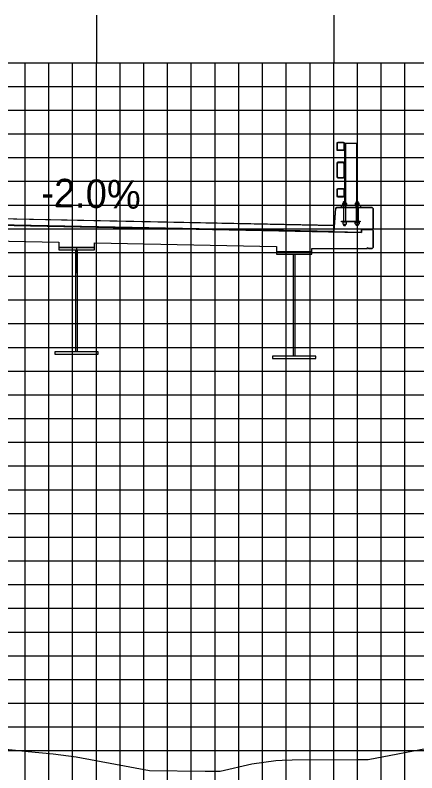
# Model space of a CAD drawing. Extents: x 1790124 to 1790467, y 442591 to 442811.
# Drawn here: x 1790296.28 to 1790313.2, y 442688.73 to 442720.67 of the extents above; entities that cross this region are included whole.
import ezdxf

# ---------------------------------------------------------------- set-up
doc = ezdxf.new("R2010")
doc.units = 0
for name, color, linetype in [('ANNOTATION', 7, 'Continuous'), ('BORDER', 7, 'Continuous'), ('D_Bridge_Framing', 7, 'Continuous'), ('D_Bridge_Railing', 7, 'Continuous'), ('D_Bridge_Superstructure', 7, 'Continuous'), ('MAJOR', 7, 'Continuous'), ('MINOR', 7, 'Continuous'), ('PATTERNING', 7, 'Continuous'), ('S_Roadway_Centerline', 7, 'Continuous'), ('SHADING', 7, 'Continuous')]:
    doc.layers.add(name, color=color, linetype=linetype)

msp = doc.modelspace()

# ---------------------------------------------------------------- linework, layer by layer
at = {"layer": 'BORDER'}
msp.add_line((1790298.862, 442710.837), (1790298.862, 442709.799), dxfattribs=at)
at = {"layer": 'D_Bridge_Framing'}
for points in [[(1790298.112, 442710.774), (1790299.612, 442710.774), (1790299.612, 442710.878), (1790298.112, 442710.878)], [(1790298.839, 442710.774), (1790298.886, 442710.774), (1790298.886, 442706.482), (1790298.839, 442706.482)], [(1790307.279, 442710.591), (1790308.779, 442710.591), (1790308.779, 442710.695), (1790307.279, 442710.695)], [(1790308.006, 442710.591), (1790308.053, 442710.591), (1790308.053, 442706.299), (1790308.006, 442706.299)], [(1790297.946, 442706.378), (1790299.779, 442706.378), (1790299.779, 442706.482), (1790297.946, 442706.482)], [(1790307.112, 442706.195), (1790308.946, 442706.195), (1790308.946, 442706.299), (1790307.112, 442706.299)]]:
    msp.add_lwpolyline(points, close=True, dxfattribs=at)
at = {"layer": 'D_Bridge_Railing'}
for p, q in [((1790309.821, 442715.264), (1790309.821, 442715.014)), ((1790309.842, 442715.264), (1790309.842, 442715.014)), ((1790310.113, 442715.306), (1790309.862, 442715.306)), ((1790310.113, 442715.285), (1790309.862, 442715.285)), ((1790310.133, 442715.014), (1790310.133, 442715.264)), ((1790310.154, 442715.014), (1790310.154, 442715.264)), ((1790310.154, 442715.264), (1790310.154, 442712.807)), ((1790310.685, 442715.264), (1790310.154, 442715.264)), ((1790310.191, 442715.264), (1790310.191, 442712.802)), ((1790310.649, 442715.264), (1790310.649, 442712.802)), ((1790310.685, 442715.264), (1790310.685, 442712.807)), ((1790309.862, 442714.993), (1790310.113, 442714.993)), ((1790309.862, 442714.972), (1790310.113, 442714.972)), ((1790309.821, 442714.421), (1790309.821, 442713.858)), ((1790309.847, 442714.421), (1790309.847, 442713.858)), ((1790310.102, 442714.472), (1790309.873, 442714.472)), ((1790310.102, 442714.446), (1790309.873, 442714.446)), ((1790310.128, 442713.858), (1790310.128, 442714.421)), ((1790310.154, 442713.858), (1790310.154, 442714.421)), ((1790309.873, 442713.832), (1790310.102, 442713.832)), ((1790309.873, 442713.806), (1790310.102, 442713.806)), ((1790309.821, 442713.306), (1790309.821, 442713.056)), ((1790309.842, 442713.306), (1790309.842, 442713.056)), ((1790310.113, 442713.347), (1790309.862, 442713.347)), ((1790310.113, 442713.327), (1790309.862, 442713.327)), ((1790310.133, 442713.056), (1790310.133, 442713.306)), ((1790310.154, 442713.056), (1790310.154, 442713.306)), ((1790309.862, 442713.035), (1790310.113, 442713.035)), ((1790309.862, 442713.014), (1790310.113, 442713.014)), ((1790310.112, 442712.797), (1790310.196, 442712.797)), ((1790310.154, 442712.807), (1790310.154, 442712.65)), ((1790310.727, 442712.797), (1790310.644, 442712.797)), ((1790310.685, 442712.807), (1790310.685, 442712.65)), ((1790310.112, 442712.556), (1790310.112, 442712.65)), ((1790310.113, 442712.735), (1790310.113, 442712.672)), ((1790310.195, 442712.735), (1790310.195, 442712.672)), ((1790310.196, 442712.556), (1790310.196, 442712.65)), ((1790310.644, 442712.735), (1790310.644, 442712.672)), ((1790310.644, 442712.556), (1790310.644, 442712.65)), ((1790310.726, 442712.735), (1790310.726, 442712.672)), ((1790310.727, 442712.556), (1790310.727, 442712.65)), ((1790310.112, 442711.986), (1790310.112, 442711.954)), ((1790310.196, 442711.986), (1790310.196, 442711.954)), ((1790310.644, 442711.986), (1790310.644, 442711.954)), ((1790310.727, 442711.986), (1790310.727, 442711.954))]:
    msp.add_line(p, q, dxfattribs=at)
for points in [[(1790310.112, 442712.745), (1790310.112, 442712.797), (1790310.123, 442712.807), (1790310.185, 442712.807), (1790310.196, 442712.797), (1790310.196, 442712.745)], [(1790310.727, 442712.745), (1790310.727, 442712.797), (1790310.717, 442712.807), (1790310.654, 442712.807), (1790310.644, 442712.797), (1790310.644, 442712.745)], [(1790310.112, 442712.556), (1790310.112, 442711.986)], [(1790310.196, 442712.556), (1790310.196, 442711.986)], [(1790310.644, 442712.556), (1790310.644, 442711.986)], [(1790310.727, 442712.556), (1790310.727, 442711.986)], [(1790310.241, 442711.954), (1790310.241, 442711.941), (1790310.067, 442711.941), (1790310.067, 442711.954)], [(1790310.088, 442711.941), (1790310.072, 442711.932), (1790310.072, 442711.869), (1790310.088, 442711.859), (1790310.22, 442711.859), (1790310.236, 442711.869), (1790310.236, 442711.932), (1790310.22, 442711.941)], [(1790310.112, 442711.859), (1790310.112, 442711.818), (1790310.123, 442711.807), (1790310.185, 442711.807), (1790310.196, 442711.818), (1790310.196, 442711.859)], [(1790310.599, 442711.954), (1790310.599, 442711.941), (1790310.772, 442711.941), (1790310.772, 442711.954)], [(1790310.751, 442711.941), (1790310.768, 442711.932), (1790310.768, 442711.869), (1790310.751, 442711.859), (1790310.619, 442711.859), (1790310.603, 442711.869), (1790310.603, 442711.932), (1790310.619, 442711.941)], [(1790310.727, 442711.859), (1790310.727, 442711.818), (1790310.717, 442711.807), (1790310.654, 442711.807), (1790310.644, 442711.818), (1790310.644, 442711.859)]]:
    msp.add_lwpolyline(points, dxfattribs=at)
for points in [[(1790310.836, 442712.65), (1790310.003, 442712.65), (1790310.003, 442712.566), (1790310.836, 442712.566)], [(1790310.836, 442712.566), (1790310.003, 442712.566), (1790310.003, 442712.556), (1790310.836, 442712.556)], [(1790310.067, 442712.65), (1790310.241, 442712.65), (1790310.241, 442712.663), (1790310.067, 442712.663)], [(1790310.072, 442712.735), (1790310.088, 442712.745), (1790310.22, 442712.745), (1790310.236, 442712.735), (1790310.236, 442712.672), (1790310.22, 442712.663), (1790310.088, 442712.663), (1790310.072, 442712.672)], [(1790310.772, 442712.65), (1790310.599, 442712.65), (1790310.599, 442712.663), (1790310.772, 442712.663)], [(1790310.768, 442712.735), (1790310.751, 442712.745), (1790310.619, 442712.745), (1790310.603, 442712.735), (1790310.603, 442712.672), (1790310.619, 442712.663), (1790310.751, 442712.663), (1790310.768, 442712.672)], [(1790310.029, 442711.986), (1790310.81, 442711.986), (1790310.81, 442711.954), (1790310.029, 442711.954)]]:
    msp.add_lwpolyline(points, close=True, dxfattribs=at)
for centre, radius, start, end in [((1790309.862, 442715.264), 0.0415, 90, 180), ((1790309.862, 442715.264), 0.0206, 90, 180), ((1790310.113, 442715.264), 0.0415, 0, 90), ((1790310.113, 442715.264), 0.0206, 0, 90), ((1790309.862, 442715.014), 0.0415, 180, 270), ((1790309.862, 442715.014), 0.0206, 180, 270), ((1790310.113, 442715.014), 0.0415, 270, 0), ((1790310.113, 442715.014), 0.0206, 270, 0), ((1790309.873, 442714.421), 0.0518, 90, 180), ((1790309.873, 442714.421), 0.0257, 90, 180), ((1790310.102, 442714.421), 0.0518, 0, 90), ((1790310.102, 442714.421), 0.0257, 0, 90), ((1790309.873, 442713.858), 0.0518, 180, 270), ((1790309.873, 442713.858), 0.0257, 180, 270), ((1790310.102, 442713.858), 0.0518, 270, 0), ((1790310.102, 442713.858), 0.0257, 270, 360), ((1790309.862, 442713.306), 0.0415, 90, 180), ((1790309.862, 442713.306), 0.0206, 90, 180), ((1790310.113, 442713.306), 0.0415, 0, 90), ((1790310.113, 442713.306), 0.0206, 0, 90), ((1790309.862, 442713.056), 0.0415, 180, 270), ((1790309.862, 442713.056), 0.0206, 180, 270), ((1790310.113, 442713.056), 0.0415, 270, 0), ((1790310.113, 442713.056), 0.0206, 270, 0), ((1790310.093, 442712.706), 0.036, 55.4339, 120), ((1790310.093, 442712.702), 0.036, 240, 304.5661), ((1790310.154, 442712.606), 0.136, 72.412, 107.588), ((1790310.154, 442712.802), 0.136, 252.412, 287.588), ((1790310.216, 442712.706), 0.036, 60, 124.5661), ((1790310.216, 442712.702), 0.036, 235.4339, 300), ((1790310.624, 442712.706), 0.036, 55.4339, 120), ((1790310.624, 442712.702), 0.036, 240, 304.5661), ((1790310.685, 442712.606), 0.136, 72.412, 107.588), ((1790310.685, 442712.802), 0.136, 252.412, 287.588), ((1790310.747, 442712.706), 0.036, 60, 124.5661), ((1790310.747, 442712.702), 0.036, 235.4339, 300)]:
    msp.add_arc(centre, radius, start, end, dxfattribs=at)
at = {"layer": 'D_Bridge_Superstructure'}
for p, q in [((1790309.776, 442712.514), (1790309.696, 442711.537)), ((1790309.776, 442712.514), (1790309.821, 442712.556)), ((1790309.821, 442712.556), (1790311.321, 442712.556)), ((1790311.362, 442712.514), (1790311.321, 442712.556)), ((1790311.362, 442712.514), (1790311.362, 442711.68)), ((1790289.696, 442712.207), (1790309.718, 442711.807)), ((1790289.696, 442711.957), (1790309.697, 442711.557)), ((1790289.696, 442711.937), (1790310.862, 442711.513)), ((1790309.696, 442711.537), (1790289.696, 442711.937)), ((1790310.862, 442711.513), (1790309.696, 442711.537)), ((1790310.862, 442711.638), (1790310.862, 442711.513)), ((1790310.862, 442711.638), (1790311.321, 442711.638)), ((1790311.321, 442711.638), (1790310.862, 442711.638)), ((1790310.862, 442711.638), (1790310.862, 442711.513)), ((1790311.321, 442711.638), (1790311.362, 442711.68)), ((1790298.112, 442710.878), (1790299.612, 442710.878)), ((1790307.279, 442710.695), (1790308.779, 442710.695)), ((1790311.112, 442710.837), (1790311.112, 442710.878)), ((1790311.112, 442710.878), (1790311.154, 442710.837))]:
    msp.add_line(p, q, dxfattribs=at)
for points in [[(1790311.321, 442711.638), (1790311.362, 442711.597), (1790311.362, 442710.878), (1790311.321, 442710.837), (1790311.154, 442710.837)], [(1790311.154, 442710.837), (1790311.321, 442710.837), (1790311.362, 442710.878), (1790311.362, 442711.597), (1790311.321, 442711.638)], [(1790290.446, 442711.062), (1790290.446, 442711.255), (1790298.112, 442711.102), (1790298.112, 442710.878)], [(1790299.612, 442710.878), (1790299.612, 442711.072), (1790307.279, 442710.918), (1790307.279, 442710.695)], [(1790308.779, 442710.695), (1790308.779, 442710.837), (1790311.112, 442710.837)], [(1790311.112, 442710.878), (1790311.112, 442710.837)], [(1790311.112, 442710.878), (1790311.154, 442710.837)]]:
    msp.add_lwpolyline(points, dxfattribs=at)
at = {"layer": 'MAJOR'}
for p, q in [((1790299.696, 442720.669), (1790299.696, 442718.665)), ((1790309.696, 442720.669), (1790309.696, 442718.665)), ((1790149.696, 442718.665), (1790429.696, 442718.665)), ((1790149.696, 442718.665), (1790429.696, 442718.665)), ((1790299.696, 442673.665), (1790299.696, 442718.665)), ((1790309.696, 442673.665), (1790309.696, 442718.665)), ((1790149.696, 442713.665), (1790429.696, 442713.665)), ((1790149.696, 442708.665), (1790429.696, 442708.665)), ((1790149.696, 442703.665), (1790429.696, 442703.665)), ((1790149.696, 442698.665), (1790429.696, 442698.665)), ((1790149.696, 442693.665), (1790429.696, 442693.665))]:
    msp.add_line(p, q, dxfattribs=at)
at = {"layer": 'MINOR'}
for p, q in [((1790296.696, 442673.665), (1790296.696, 442718.665)), ((1790297.696, 442673.665), (1790297.696, 442718.665)), ((1790298.696, 442673.665), (1790298.696, 442718.665)), ((1790300.696, 442673.665), (1790300.696, 442718.665)), ((1790301.696, 442673.665), (1790301.696, 442718.665)), ((1790302.696, 442673.665), (1790302.696, 442718.665)), ((1790303.696, 442673.665), (1790303.696, 442718.665)), ((1790304.696, 442673.665), (1790304.696, 442718.665)), ((1790305.696, 442673.665), (1790305.696, 442718.665)), ((1790306.696, 442673.665), (1790306.696, 442718.665)), ((1790307.696, 442673.665), (1790307.696, 442718.665)), ((1790308.696, 442673.665), (1790308.696, 442718.665)), ((1790310.696, 442673.665), (1790310.696, 442718.665)), ((1790311.696, 442673.665), (1790311.696, 442718.665)), ((1790312.696, 442673.665), (1790312.696, 442718.665)), ((1790149.696, 442717.665), (1790429.696, 442717.665)), ((1790149.696, 442716.665), (1790429.696, 442716.665)), ((1790149.696, 442715.665), (1790429.696, 442715.665)), ((1790149.696, 442714.665), (1790429.696, 442714.665)), ((1790149.696, 442712.665), (1790429.696, 442712.665)), ((1790149.696, 442711.665), (1790429.696, 442711.665)), ((1790149.696, 442710.665), (1790429.696, 442710.665)), ((1790149.696, 442709.665), (1790429.696, 442709.665)), ((1790149.696, 442707.665), (1790429.696, 442707.665)), ((1790149.696, 442706.665), (1790429.696, 442706.665)), ((1790149.696, 442705.665), (1790429.696, 442705.665)), ((1790149.696, 442704.665), (1790429.696, 442704.665)), ((1790149.696, 442702.665), (1790429.696, 442702.665)), ((1790149.696, 442701.665), (1790429.696, 442701.665)), ((1790149.696, 442700.665), (1790429.696, 442700.665)), ((1790149.696, 442699.665), (1790429.696, 442699.665)), ((1790149.696, 442697.665), (1790429.696, 442697.665)), ((1790149.696, 442696.665), (1790429.696, 442696.665)), ((1790149.696, 442695.665), (1790429.696, 442695.665)), ((1790149.696, 442694.665), (1790429.696, 442694.665)), ((1790149.696, 442692.665), (1790429.696, 442692.665)), ((1790149.696, 442691.665), (1790429.696, 442691.665)), ((1790149.696, 442690.665), (1790429.696, 442690.665)), ((1790149.696, 442689.665), (1790429.696, 442689.665))]:
    msp.add_line(p, q, dxfattribs=at)
at = {"layer": 'PATTERNING'}
for p, q in [((1790309.821, 442712.556), (1790309.776, 442712.514)), ((1790311.321, 442712.556), (1790309.821, 442712.556)), ((1790311.362, 442712.514), (1790311.321, 442712.556)), ((1790311.362, 442711.68), (1790311.362, 442712.514)), ((1790309.696, 442711.537), (1790310.862, 442711.513)), ((1790310.862, 442711.513), (1790310.862, 442711.638)), ((1790310.862, 442711.638), (1790311.321, 442711.638)), ((1790311.321, 442711.638), (1790311.362, 442711.68))]:
    msp.add_line(p, q, dxfattribs=at)
msp.add_lwpolyline([(1790309.776, 442712.514), (1790309.718, 442711.807), (1790309.697, 442711.557), (1790309.696, 442711.537)], dxfattribs=at)
at = {"layer": 'S_Roadway_Centerline'}
msp.add_lwpolyline([(1790294.527, 442689.874), (1790296.831, 442689.629), (1790297.881, 442689.537), (1790298.84, 442689.403), (1790301.935, 442688.832), (1790304.276, 442688.796), (1790304.907, 442688.793), (1790306.245, 442689.105), (1790307.261, 442689.253), (1790307.527, 442689.266), (1790307.951, 442689.284), (1790310.695, 442689.293), (1790311.142, 442689.289), (1790316.737, 442690.355)], dxfattribs=at)
at = {"layer": 'SHADING'}
for p, q in [((1790289.696, 442711.957), (1790309.697, 442711.557)), ((1790289.696, 442711.957), (1790309.697, 442711.557)), ((1790309.697, 442711.557), (1790309.718, 442711.807)), ((1790309.697, 442711.557), (1790309.718, 442711.807))]:
    msp.add_line(p, q, dxfattribs=at)
msp.add_lwpolyline([(1790309.718, 442711.807), (1790292.825, 442712.145), (1790289.696, 442712.207)], dxfattribs=at)
msp.add_lwpolyline([(1790309.718, 442711.807), (1790292.825, 442712.145), (1790289.696, 442712.207)], dxfattribs=at)

# ---------------------------------------------------------------- texts
at = {"layer": 'ANNOTATION'}
msp.add_text('-2.0%', height=1.2, rotation=358.8542, dxfattribs=at).set_placement((1790297.364, 442712.588))

doc.saveas('drawing.dxf')
